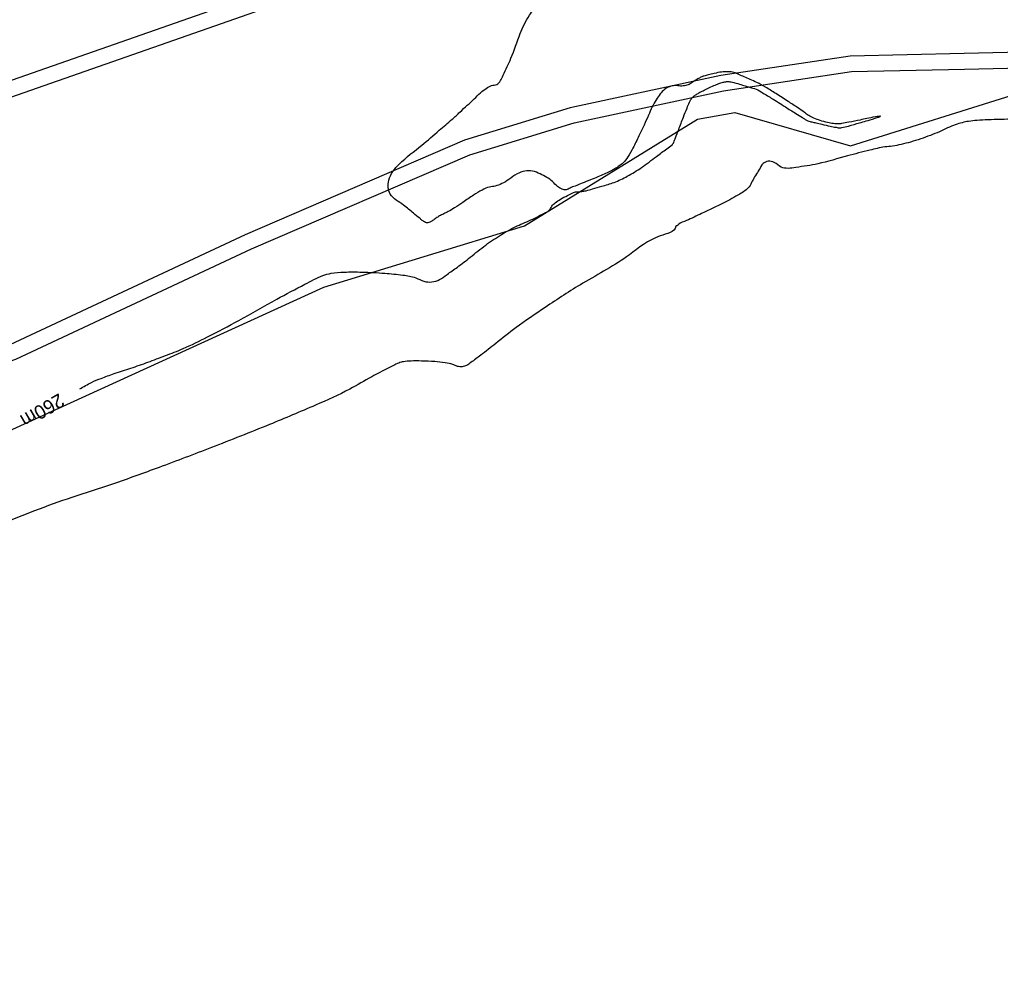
# Model space of a CAD drawing. Extents: x -478495 to -472450, y -1118050 to -1113745.
# Drawn here: x -475258.9 to -475132.3, y -1117593.9 to -1117469.7 of the extents above; entities that cross this region are included whole.
import ezdxf

# ---------------------------------------------------------------- set-up
doc = ezdxf.new("R2010")
doc.units = 0
for name, color, linetype in [('hranice kú', 7, 'Continuous'), ('ObPÚ', 7, 'Continuous'), ('vodní plochy', 7, 'Continuous'), ('Vrstevnice_hlavni', 7, 'Continuous'), ('Vrstevnice_popis', 7, 'Continuous'), ('Vrstevnice_vedlejsi', 7, 'Continuous')]:
    doc.layers.add(name, color=color, linetype=linetype)

msp = doc.modelspace()

# ---------------------------------------------------------------- linework, layer by layer
at = {"layer": 'hranice kú'}
for p, q in [((-475151.66, -1117485.95), (-475125.25, -1117477.72)), ((-475193.73, -1117496.31), (-475171.39, -1117482.52)), ((-475171.39, -1117482.52), (-475166.58, -1117481.66)), ((-475166.58, -1117481.66), (-475151.66, -1117485.95)), ((-475219.63, -1117504.21), (-475193.73, -1117496.31)), ((-475264.74, -1117524.8), (-475219.63, -1117504.21))]:
    msp.add_line(p, q, dxfattribs=at)
at = {"layer": 'ObPÚ'}
for p, q in [((-475151.66, -1117485.95), (-475125.25, -1117477.72)), ((-475193.73, -1117496.31), (-475171.39, -1117482.52)), ((-475171.39, -1117482.52), (-475166.58, -1117481.66)), ((-475166.58, -1117481.66), (-475151.66, -1117485.95)), ((-475219.63, -1117504.21), (-475193.73, -1117496.31)), ((-475264.74, -1117524.8), (-475219.63, -1117504.21))]:
    msp.add_line(p, q, dxfattribs=at)
at = {"layer": 'vodní plochy'}
for points in [[(-474935.79, -1117380.13), (-474970.76, -1117382.06), (-474998.37, -1117384.3), (-475014.15, -1117387.26), (-475023.17, -1117390.37), (-475039.26, -1117395.97), (-475098.28, -1117418.21), (-475194.88, -1117454.72), (-475264.36, -1117479.06), (-475325.6, -1117501.72), (-475374.22, -1117518.91), (-475396.67, -1117525.33), (-475424.9, -1117531.34), (-475499.58, -1117550.23)], [(-475580.89, -1117574.7), (-475558.33, -1117567.97), (-475499.08, -1117552.17), (-475424.44, -1117533.29), (-475396.19, -1117527.27), (-475373.61, -1117520.82), (-475324.92, -1117503.6), (-475263.68, -1117480.94), (-475194.19, -1117456.6), (-475097.57, -1117420.08), (-475038.58, -1117397.84), (-475022.51, -1117392.26), (-475013.64, -1117389.2), (-474998.1, -1117386.29), (-474970.62, -1117384.06), (-474937.15, -1117382.2)], [(-475124.07, -1117473.75), (-475136.96, -1117474.05), (-475151.7, -1117474.39), (-475168.4, -1117476.9), (-475187.85, -1117481.06), (-475201.5, -1117485.24), (-475229.8, -1117497.45), (-475260.18, -1117511.67), (-475291.87, -1117522.84), (-475334.09, -1117537.24), (-475368.7, -1117548.41), (-475393.33, -1117553.13), (-475405.89, -1117553.26), (-475433.3, -1117548.97), (-475447.88, -1117549.53), (-475456.34, -1117551.37), (-475467.42, -1117555.72), (-475480.14, -1117563.12), (-475517.88, -1117592.15)], [(-475516.83, -1117593.87), (-475479.02, -1117564.78), (-475466.54, -1117557.52), (-475455.76, -1117553.29), (-475447.62, -1117551.52), (-475433.42, -1117550.98), (-475406.03, -1117555.27), (-475393.13, -1117555.13), (-475368.2, -1117550.35), (-475333.46, -1117539.14), (-475291.22, -1117524.73), (-475259.43, -1117513.52), (-475228.98, -1117499.27), (-475200.81, -1117487.12), (-475187.34, -1117483), (-475168.04, -1117478.86), (-475151.53, -1117476.39), (-475136.91, -1117476.05), (-475124.02, -1117475.75)]]:
    msp.add_lwpolyline(points, dxfattribs=at)
at = {"layer": 'Vrstevnice_hlavni'}
for points in [[(-475329.32, -1117471.97), (-475322.85, -1117471.51), (-475318.35, -1117471.85), (-475312.61, -1117472.76), (-475305.62, -1117474.25), (-475299.98, -1117475.02), (-475295.68, -1117475.08), (-475292.74, -1117474.43), (-475289.02, -1117473.58), (-475284.53, -1117472.52), (-475279.25, -1117471.26), (-475274.2, -1117470.11), (-475269.37, -1117469.07), (-475264.75, -1117468.15), (-475259.99, -1117465.41), (-475255.09, -1117460.86), (-475250.04, -1117454.5), (-475246.13, -1117450.2), (-475243.35, -1117447.97), (-475241.71, -1117447.8), (-475240.01, -1117447.57), (-475238.27, -1117447.26), (-475236.48, -1117446.89), (-475234.85, -1117446.49), (-475233.39, -1117446.07), (-475232.11, -1117445.62), (-475230.38, -1117445.27), (-475228.23, -1117445.02), (-475225.63, -1117444.86), (-475222.24, -1117443.59), (-475218.05, -1117441.22), (-475213.06, -1117437.73), (-475209.06, -1117435.31), (-475206.06, -1117433.94), (-475204.04, -1117433.64), (-475202.65, -1117433.4), (-475201.88, -1117433.25), (-475201.73, -1117433.17), (-475201.19, -1117433.08), (-475200.27, -1117432.98), (-475198.96, -1117432.88), (-475198.19, -1117432.98), (-475197.94, -1117433.29), (-475198.22, -1117433.8), (-475197.08, -1117435.08), (-475194.52, -1117437.12), (-475190.54, -1117439.92), (-475187.72, -1117442.24), (-475186.06, -1117444.1), (-475185.56, -1117445.5), (-475185.44, -1117447.04), (-475185.68, -1117448.74), (-475186.3, -1117450.59), (-475186.24, -1117451.64), (-475185.5, -1117451.9), (-475184.08, -1117451.35), (-475182.79, -1117450.87), (-475181.64, -1117450.45), (-475180.63, -1117450.09), (-475179.88, -1117449.82), (-475179.4, -1117449.65), (-475178.97, -1117449.5)], [(-475152.8, -1117483.1), (-475153.23, -1117483.15), (-475153.84, -1117483.1), (-475154.61, -1117482.95), (-475155.56, -1117482.7), (-475156.36, -1117482.4), (-475157.04, -1117482.05), (-475157.57, -1117481.66), (-475158.45, -1117481.05), (-475159.69, -1117480.24), (-475161.28, -1117479.21), (-475162.63, -1117478.4), (-475163.73, -1117477.79), (-475164.58, -1117477.4), (-475165.36, -1117477.06), (-475166.06, -1117476.76), (-475166.69, -1117476.51), (-475167.43, -1117476.4), (-475168.28, -1117476.44), (-475169.24, -1117476.62), (-475170, -1117476.79), (-475170.57, -1117476.96), (-475170.95, -1117477.11), (-475171.37, -1117477.33), (-475171.84, -1117477.62), (-475172.34, -1117477.97), (-475172.92, -1117478.18), (-475173.58, -1117478.25), (-475174.32, -1117478.19), (-475175.01, -1117478.33), (-475175.64, -1117478.69), (-475176.21, -1117479.27), (-475176.74, -1117480.01), (-475177.25, -1117480.94), (-475177.73, -1117482.03), (-475178.3, -1117483.28), (-475178.97, -1117484.69), (-475179.73, -1117486.25), (-475180.41, -1117487.41), (-475181, -1117488.18), (-475181.5, -1117488.56), (-475182.07, -1117488.93), (-475182.72, -1117489.28), (-475183.44, -1117489.62), (-475184.28, -1117489.98), (-475185.23, -1117490.38), (-475186.3, -1117490.8), (-475187.18, -1117491.16), (-475187.86, -1117491.43), (-475188.35, -1117491.64), (-475188.89, -1117491.56), (-475189.48, -1117491.21), (-475190.12, -1117490.58), (-475190.87, -1117490.04), (-475191.73, -1117489.6), (-475192.7, -1117489.24), (-475193.69, -1117489.24), (-475194.7, -1117489.6), (-475195.74, -1117490.32), (-475196.68, -1117490.85), (-475197.52, -1117491.17), (-475198.26, -1117491.29), (-475199.2, -1117491.68), (-475200.34, -1117492.34), (-475201.68, -1117493.27), (-475202.77, -1117493.98), (-475203.6, -1117494.47), (-475204.17, -1117494.75), (-475204.7, -1117495.03), (-475205.18, -1117495.32), (-475205.62, -1117495.63), (-475205.98, -1117495.83), (-475206.24, -1117495.92), (-475206.41, -1117495.9), (-475206.64, -1117495.79), (-475206.93, -1117495.6), (-475207.27, -1117495.33), (-475208.08, -1117494.67), (-475209.34, -1117493.62), (-475211.07, -1117492.19), (-475211.25, -1117490.42), (-475209.9, -1117488.32), (-475207.01, -1117485.89), (-475204.74, -1117483.96), (-475203.09, -1117482.54), (-475202.07, -1117481.61), (-475201.12, -1117480.73), (-475200.24, -1117479.91), (-475199.43, -1117479.12), (-475198.68, -1117478.55), (-475197.98, -1117478.19), (-475197.33, -1117478.03), (-475196.5, -1117476.86), (-475195.49, -1117474.67), (-475194.28, -1117471.47), (-475193.1, -1117469.11), (-475191.94, -1117467.6)], [(-475251.17, -1117517.36), (-475249.64, -1117516.52), (-475248.41, -1117516), (-475246.72, -1117515.39), (-475244.56, -1117514.68), (-475242.36, -1117513.91), (-475240.11, -1117513.06), (-475237.82, -1117512.16), (-475234.66, -1117510.64), (-475230.62, -1117508.51), (-475225.72, -1117505.77), (-475222.09, -1117503.84), (-475219.76, -1117502.73), (-475218.71, -1117502.43), (-475217.03, -1117502.27), (-475214.72, -1117502.27), (-475211.77, -1117502.42), (-475209.46, -1117502.66), (-475207.78, -1117503.01), (-475206.73, -1117503.46), (-475205.71, -1117503.54), (-475204.71, -1117503.25), (-475203.73, -1117502.59), (-475202.41, -1117501.63), (-475200.75, -1117500.36), (-475198.74, -1117498.78), (-475196.72, -1117497.43), (-475194.7, -1117496.32), (-475192.67, -1117495.43), (-475191.24, -1117494.71), (-475190.42, -1117494.15), (-475190.2, -1117493.75), (-475189.76, -1117493.32), (-475189.09, -1117492.86), (-475188.19, -1117492.38), (-475187.51, -1117492.05), (-475187.05, -1117491.89), (-475186.81, -1117491.9), (-475186.52, -1117491.88), (-475186.17, -1117491.83), (-475185.76, -1117491.76), (-475184.95, -1117491.54), (-475183.76, -1117491.19), (-475182.16, -1117490.69), (-475180.46, -1117489.89), (-475178.63, -1117488.77), (-475176.69, -1117487.33), (-475175.37, -1117486.35), (-475174.68, -1117485.83), (-475174.61, -1117485.77), (-475174.56, -1117485.69), (-475174.51, -1117485.61), (-475174.47, -1117485.52), (-475174.24, -1117484.93), (-475173.83, -1117483.85), (-475173.22, -1117482.27), (-475172.75, -1117481.1), (-475172.43, -1117480.34), (-475172.25, -1117479.99), (-475171.99, -1117479.67), (-475171.65, -1117479.39), (-475171.22, -1117479.13), (-475170.68, -1117478.85), (-475170.04, -1117478.54), (-475169.29, -1117478.2), (-475168.64, -1117477.94), (-475168.09, -1117477.77), (-475167.64, -1117477.68), (-475167.07, -1117477.71), (-475166.39, -1117477.86), (-475165.59, -1117478.13), (-475164.93, -1117478.33), (-475164.42, -1117478.48), (-475164.05, -1117478.56), (-475163.2, -1117479), (-475161.87, -1117479.8), (-475160.05, -1117480.94), (-475158.71, -1117481.79), (-475157.86, -1117482.33), (-475157.48, -1117482.56), (-475157.15, -1117482.73), (-475156.87, -1117482.84), (-475156.62, -1117482.89), (-475156.11, -1117483), (-475155.33, -1117483.18), (-475154.28, -1117483.43), (-475153.5, -1117483.58), (-475152.99, -1117483.65), (-475152.76, -1117483.62), (-475151.92, -1117483.41), (-475150.49, -1117483), (-475148.47, -1117482.41), (-475147.78, -1117482.16), (-475148.42, -1117482.23), (-475150.4, -1117482.64), (-475151.86, -1117482.93), (-475152.8, -1117483.1)]]:
    msp.add_spline(points, degree=3, dxfattribs=at)
at = {"layer": 'Vrstevnice_vedlejsi'}
for points in [[(-475076.41, -1117477.38), (-475077.57, -1117477.36), (-475078.93, -1117477.29), (-475080.47, -1117477.19), (-475082.19, -1117477.04), (-475083.4, -1117476.97), (-475084.08, -1117476.99), (-475084.25, -1117477.08), (-475084.62, -1117477.18), (-475085.19, -1117477.28), (-475085.95, -1117477.38), (-475087.24, -1117477.48), (-475089.06, -1117477.58), (-475091.41, -1117477.68), (-475093.14, -1117477.77), (-475094.24, -1117477.84), (-475094.72, -1117477.9), (-475095.37, -1117478.12), (-475096.19, -1117478.5), (-475097.19, -1117479.03), (-475097.95, -1117479.42), (-475098.46, -1117479.67), (-475098.74, -1117479.77), (-475099.4, -1117479.84), (-475100.46, -1117479.88), (-475101.91, -1117479.9), (-475103.03, -1117479.85), (-475103.82, -1117479.73), (-475104.29, -1117479.56), (-475104.69, -1117479.38), (-475105.05, -1117479.19), (-475105.35, -1117478.99), (-475105.81, -1117478.92), (-475106.44, -1117478.97), (-475107.23, -1117479.16), (-475108.01, -1117479.29), (-475108.81, -1117479.39), (-475109.6, -1117479.44), (-475110.46, -1117479.55), (-475111.38, -1117479.72), (-475112.37, -1117479.96), (-475113.57, -1117480.29), (-475115, -1117480.72), (-475116.65, -1117481.24), (-475118.19, -1117481.58), (-475119.63, -1117481.75), (-475120.97, -1117481.73), (-475122.17, -1117481.78), (-475123.23, -1117481.9), (-475124.14, -1117482.08), (-475125.36, -1117482.23), (-475126.89, -1117482.35), (-475128.73, -1117482.45), (-475130.51, -1117482.52), (-475132.24, -1117482.57), (-475133.92, -1117482.61), (-475135.3, -1117482.69), (-475136.4, -1117482.81), (-475137.21, -1117482.98), (-475138.11, -1117483.25), (-475139.1, -1117483.65), (-475140.17, -1117484.15), (-475141.33, -1117484.62), (-475142.57, -1117485.07), (-475143.9, -1117485.48), (-475145.11, -1117485.79), (-475146.22, -1117486.01), (-475147.21, -1117486.12), (-475149.15, -1117486.54), (-475152.03, -1117487.26), (-475155.85, -1117488.29), (-475158.71, -1117488.77), (-475160.59, -1117488.71), (-475161.49, -1117488.11), (-475162.27, -1117487.96), (-475162.92, -1117488.27), (-475163.43, -1117489.04), (-475163.91, -1117489.79), (-475164.33, -1117490.53), (-475164.72, -1117491.25), (-475165.93, -1117492.19), (-475167.98, -1117493.34), (-475170.87, -1117494.7), (-475172.83, -1117495.63), (-475173.85, -1117496.14), (-475173.95, -1117496.22), (-475174.03, -1117496.27), (-475174.09, -1117496.3), (-475174.13, -1117496.3), (-475174.16, -1117496.31), (-475174.18, -1117496.33), (-475174.19, -1117496.36), (-475176.2, -1117497.6), (-475180.2, -1117500.05), (-475186.21, -1117503.72), (-475191.08, -1117506.84), (-475194.83, -1117509.44)], [(-475194.83, -1117509.44), (-475197.46, -1117511.5), (-475199.39, -1117513.01), (-475200.65, -1117513.95), (-475201.22, -1117514.33), (-475201.8, -1117514.5), (-475202.39, -1117514.45), (-475203, -1117514.19), (-475203.98, -1117513.99), (-475205.33, -1117513.84), (-475207.04, -1117513.76), (-475208.39, -1117513.76), (-475209.37, -1117513.85), (-475209.98, -1117514.02), (-475211.34, -1117514.67), (-475213.45, -1117515.79), (-475216.3, -1117517.39), (-475220.71, -1117519.45), (-475226.67, -1117521.96), (-475234.17, -1117524.94), (-475240.93, -1117527.5), (-475246.93, -1117529.64), (-475252.2, -1117531.37), (-475257, -1117533.1), (-475261.35, -1117534.84), (-475265.24, -1117536.58), (-475268.28, -1117537.92), (-475270.48, -1117538.84), (-475271.83, -1117539.37), (-475273.71, -1117540.17), (-475276.1, -1117541.26), (-475279.02, -1117542.64), (-475281.2, -1117543.56), (-475282.64, -1117544.03), (-475283.34, -1117544.05), (-475284.64, -1117544.57), (-475286.53, -1117545.61), (-475289.01, -1117547.16), (-475292.01, -1117548.39), (-475295.51, -1117549.31), (-475299.53, -1117549.91), (-475303.11, -1117550.61), (-475306.26, -1117551.41), (-475308.97, -1117552.3), (-475311.94, -1117553.42), (-475315.18, -1117554.77), (-475318.67, -1117556.35), (-475321.49, -1117557.66), (-475323.62, -1117558.69), (-475325.07, -1117559.44), (-475326.32, -1117560.02), (-475327.38, -1117560.44), (-475328.24, -1117560.68), (-475329, -1117560.88), (-475329.67, -1117561.02), (-475330.23, -1117561.12), (-475330.96, -1117561.3), (-475331.86, -1117561.56), (-475332.91, -1117561.91), (-475338.74, -1117563.11), (-475349.34, -1117565.16), (-475364.71, -1117568.05), (-475375.01, -1117569.99), (-475380.24, -1117570.97), (-475380.4, -1117570.99), (-475380.65, -1117571.05), (-475381, -1117571.15), (-475381.45, -1117571.3), (-475381.86, -1117571.52), (-475382.21, -1117571.8), (-475382.52, -1117572.15), (-475382.8, -1117572.41), (-475383.07, -1117572.58), (-475383.32, -1117572.66), (-475384.25, -1117573.45), (-475385.87, -1117574.95), (-475388.17, -1117577.17), (-475390.77, -1117579.24), (-475393.66, -1117581.18), (-475395.95, -1117582.5)]]:
    msp.add_spline(points, degree=3, dxfattribs=at)

# ---------------------------------------------------------------- texts
at = {"layer": 'Vrstevnice_popis'}
msp.add_text(' 260m ', height=1.8, rotation=210.2386, dxfattribs=at).set_placement((-475253.26, -1117517.53))

doc.saveas('drawing.dxf')
